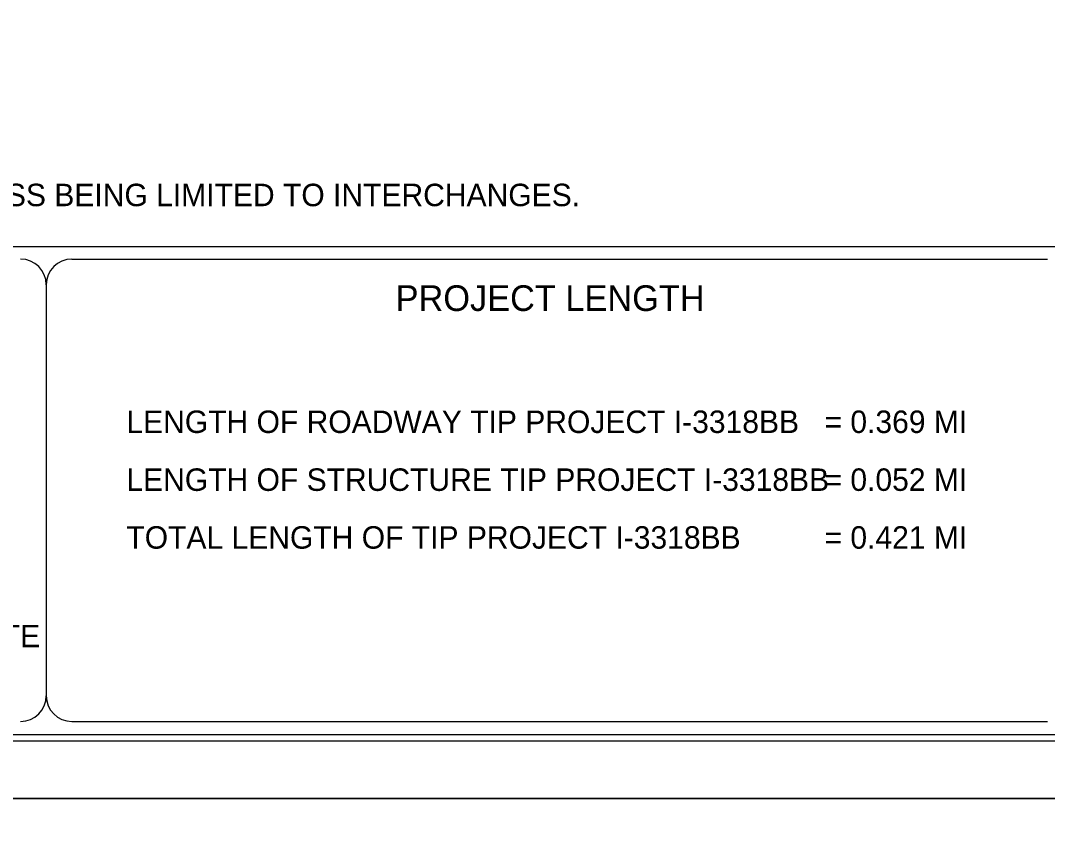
# Model space of a CAD drawing. Extents: x 2241278 to 2254132, y 649924 to 670434.
# Drawn here: x 2247319 to 2249319, y 660843 to 662414 of the extents above; entities that cross this region are included whole.
import ezdxf

# ---------------------------------------------------------------- set-up
doc = ezdxf.new("R2010")
doc.units = 0
for name, color, linetype in [('Sheet Block Title CELL', 7, 'Continuous'), ('Sheet Cutting Line CELL', 7, 'Continuous'), ('Sheet Data Field CELL', 7, 'Continuous'), ('Sheet Plot Border Inside CELL', 7, 'Continuous'), ('Sheet Plot Border Outside CELL', 7, 'Continuous'), ('Sheet Title CELL', 7, 'Continuous')]:
    doc.layers.add(name, color=color, linetype=linetype)

msp = doc.modelspace()

# ---------------------------------------------------------------- linework, layer by layer
at = {"layer": 'Sheet Cutting Line CELL'}
for p, q in [((2244558.8, 660899.2), (2252978.8, 660899.2)), ((2252978.8, 660899.2), (2244558.8, 660899.2))]:
    msp.add_line(p, q, dxfattribs=at)
at = {"layer": 'Sheet Plot Border Inside CELL'}
msp.add_lwpolyline([(2244623.8, 661011.4), (2252956.3, 661011.4), (2252956.3, 666286.9), (2244623.8, 666286.9)], close=True, dxfattribs=at)
at = {"layer": 'Sheet Plot Border Outside CELL'}
for points in [[(2252978.8, 666399.1), (2244558.8, 666399.1), (2244558.8, 660899.2), (2252978.8, 660899.2)], [(2244558.8, 655399.2), (2252978.8, 655399.2), (2252978.8, 660899.2), (2244558.8, 660899.2)]]:
    msp.add_lwpolyline(points, close=True, dxfattribs=at)
at = {"layer": 'Sheet Title CELL'}
for p, q in [((2245718.8, 661974.2), (2252818.8, 661974.2)), ((2247418.8, 661949.1), (2249318.8, 661949.1)), ((2247368.8, 661899.2), (2247368.8, 661099.2))]:
    msp.add_line(p, q, dxfattribs=at)
for points in [[(2247418.8, 661049.1), (2249318.8, 661049.1)], [(2245443.8, 661024.1), (2252843.8, 661024.1)]]:
    msp.add_lwpolyline(points, dxfattribs=at)
for centre, start, end in [((2247318.8, 661899.4), 0, 90), ((2247418.8, 661899.4), 90, 180), ((2247318.8, 661099.4), 270, 360), ((2247418.8, 661099.4), 180, 270)]:
    msp.add_arc(centre, 50, start, end, dxfattribs=at)

# ---------------------------------------------------------------- texts
at = {"layer": 'Sheet Block Title CELL'}
msp.add_text('THIS IS A CONTROLLED-ACCESS PROJECT WITH ACCESS BEING LIMITED TO INTERCHANGES.', height=43.751, dxfattribs=at).set_placement((2245720.2, 662052.4))
at = {"layer": 'Sheet Data Field CELL'}
for s, height, p in [('LENGTH OF ROADWAY TIP PROJECT I-3318BB', 43.751, (2247524.9, 661610.9)), ('= 0.369 MI', 43.75, (2248884.5, 661610.9)), ('LENGTH OF STRUCTURE TIP PROJECT I-3318BB', 43.751, (2247524.9, 661498.2)), ('= 0.052 MI', 43.75, (2248884.5, 661498.2)), ('TOTAL LENGTH OF TIP PROJECT I-3318BB', 43.751, (2247524.9, 661385.7)), ('= 0.421 MI', 43.75, (2248884.5, 661385.7))]:
    msp.add_text(s, height=height, dxfattribs=at).set_placement(p)
msp.add_text('FUNC CLASS=INTERSTATE ', height=43.75, rotation=360, dxfattribs=at).set_placement((2246588.2, 661193.7))
at = {"layer": 'Sheet Title CELL'}
msp.add_text('PROJECT LENGTH', height=49.998, rotation=360, dxfattribs=at).set_placement((2248049.3, 661848.4))

doc.saveas('drawing.dxf')
